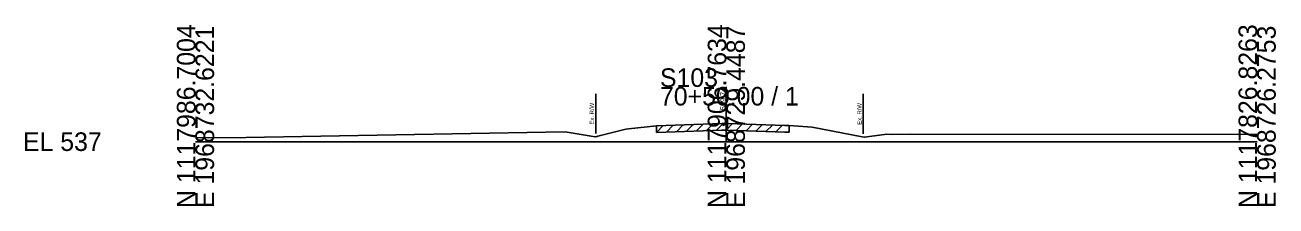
# Model space of a CAD drawing. Extents: x -26 to 163, y -10 to 24018.
# Drawn here: x -25.7 to 162.8, y 18490.3 to 18517.6 of the extents above; entities that cross this region are included whole.
import ezdxf

# ---------------------------------------------------------------- set-up
doc = ezdxf.new("R2010")
doc.units = 0
for name, color, linetype in [('RD_GPK_XS_Cell', 7, 'Continuous'), ('RD_XS_ExGround', 7, 'Continuous'), ('RD_XS_ExPaveRet', 7, 'Continuous'), ('RD_XS_ExRW', 7, 'Continuous'), ('RD_XS_TX_Elev_EX', 7, 'Continuous')]:
    doc.layers.add(name, color=color, linetype=linetype)

msp = doc.modelspace()

# ---------------------------------------------------------------- linework, layer by layer
at = {"layer": 'RD_GPK_XS_Cell'}
for p, q in [((80, 18500), (80, 18508.25)), ((0, 18500), (80, 18500)), ((80, 18500), (160, 18500))]:
    msp.add_line(p, q, dxfattribs=at)
at = {"layer": 'RD_XS_ExGround'}
msp.add_lwpolyline([(0, 18500.58), (7.58, 18500.65), (52.81, 18501.42), (55.72, 18501.46), (59.94, 18500.78), (60.31, 18500.72), (60.64, 18500.81), (64.88, 18501.9), (65.26, 18501.94), (69.47, 18502.4), (79.32, 18502.72), (80.17, 18502.75), (88.83, 18502.45), (89.47, 18502.42), (92.95, 18502.18), (100.46, 18500.73), (100.81, 18500.66), (104.19, 18501.13), (105.12, 18501.09), (107.83, 18501.12), (160, 18501.1)], dxfattribs=at)
at = {"layer": 'RD_XS_ExPaveRet'}
for p, q in [((75.47, 18501.59), (76.5, 18502.63)), ((76.97, 18501.64), (78, 18502.68)), ((78.47, 18501.69), (79.5, 18502.73)), ((79.97, 18501.74), (80.95, 18502.72)), ((81.47, 18501.7), (82.44, 18502.67)), ((82.97, 18501.65), (83.94, 18502.62)), ((69.47, 18501.4), (70.5, 18502.43)), ((69.47, 18501.4), (69.47, 18502.4)), ((69.47, 18501.4), (79.32, 18501.72)), ((70.97, 18501.45), (72, 18502.48)), ((72.47, 18501.5), (73.5, 18502.53)), ((73.97, 18501.54), (75, 18502.58)), ((79.32, 18501.72), (80.17, 18501.75)), ((80.17, 18501.75), (88.83, 18501.45)), ((84.47, 18501.6), (85.44, 18502.57)), ((85.97, 18501.55), (86.94, 18502.51)), ((87.47, 18501.49), (88.44, 18502.46)), ((88.83, 18501.45), (89.47, 18501.42)), ((89.47, 18502.42), (89.47, 18501.42))]:
    msp.add_line(p, q, dxfattribs=at)
at = {"layer": 'RD_XS_ExRW'}
for p, q in [((60.31, 18507.22), (60.31, 18501.22)), ((100.64, 18507.19), (100.64, 18501.19))]:
    msp.add_line(p, q, dxfattribs=at)

# ---------------------------------------------------------------- texts
at = {"layer": 'RD_GPK_XS_Cell'}
for s, p in [('N 1117986.7004', (0, 18490)), ('E 1968732.6221', (2.8, 18490)), ('N 1117906.7634', (80, 18490)), ('E 1968729.4487', (82.8, 18490)), ('N 1117826.8263', (160, 18490)), ('E 1968726.2753', (162.8, 18490))]:
    msp.add_text(s, height=2.8, rotation=90, dxfattribs=at).set_placement(p)
for s, p in [('S103', (70, 18508.25)), ('70+50.00 / 1', (70, 18505.45)), ('EL 537', (-26, 18498.6))]:
    msp.add_text(s, height=2.8, dxfattribs=at).set_placement(p)
at = {"layer": 'RD_XS_ExRW'}
for p in [(60.06, 18502.57), (100.39, 18502.54)]:
    msp.add_text('Ex. R/W ', height=0.65, rotation=90, dxfattribs=at).set_placement(p)
at = {"layer": 'RD_XS_TX_Elev_EX'}
msp.add_text('539.74', height=0.8, rotation=90, dxfattribs=at).set_placement((79.9, 18504.74))

doc.saveas('drawing.dxf')
